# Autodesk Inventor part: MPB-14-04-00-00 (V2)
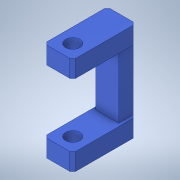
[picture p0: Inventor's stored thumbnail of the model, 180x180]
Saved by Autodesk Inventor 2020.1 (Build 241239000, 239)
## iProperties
Created: 2020-04
Part Number: MPB-14-04-00-00 (V2)
Material: Al 7075
Document SubType Name: Modeling
Designer: Safarabadi
Density: 2.7 g/cm^3
Appearance: Aluminum - Flat
Author: Safarabadi
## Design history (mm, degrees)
derived "MPB-14-04-00-00.ipt"
feature "Solid1::MPB-14-04-00-00.ipt" dims "d0" = 10
tag "TaggingFeature1"
body "Solid1"
